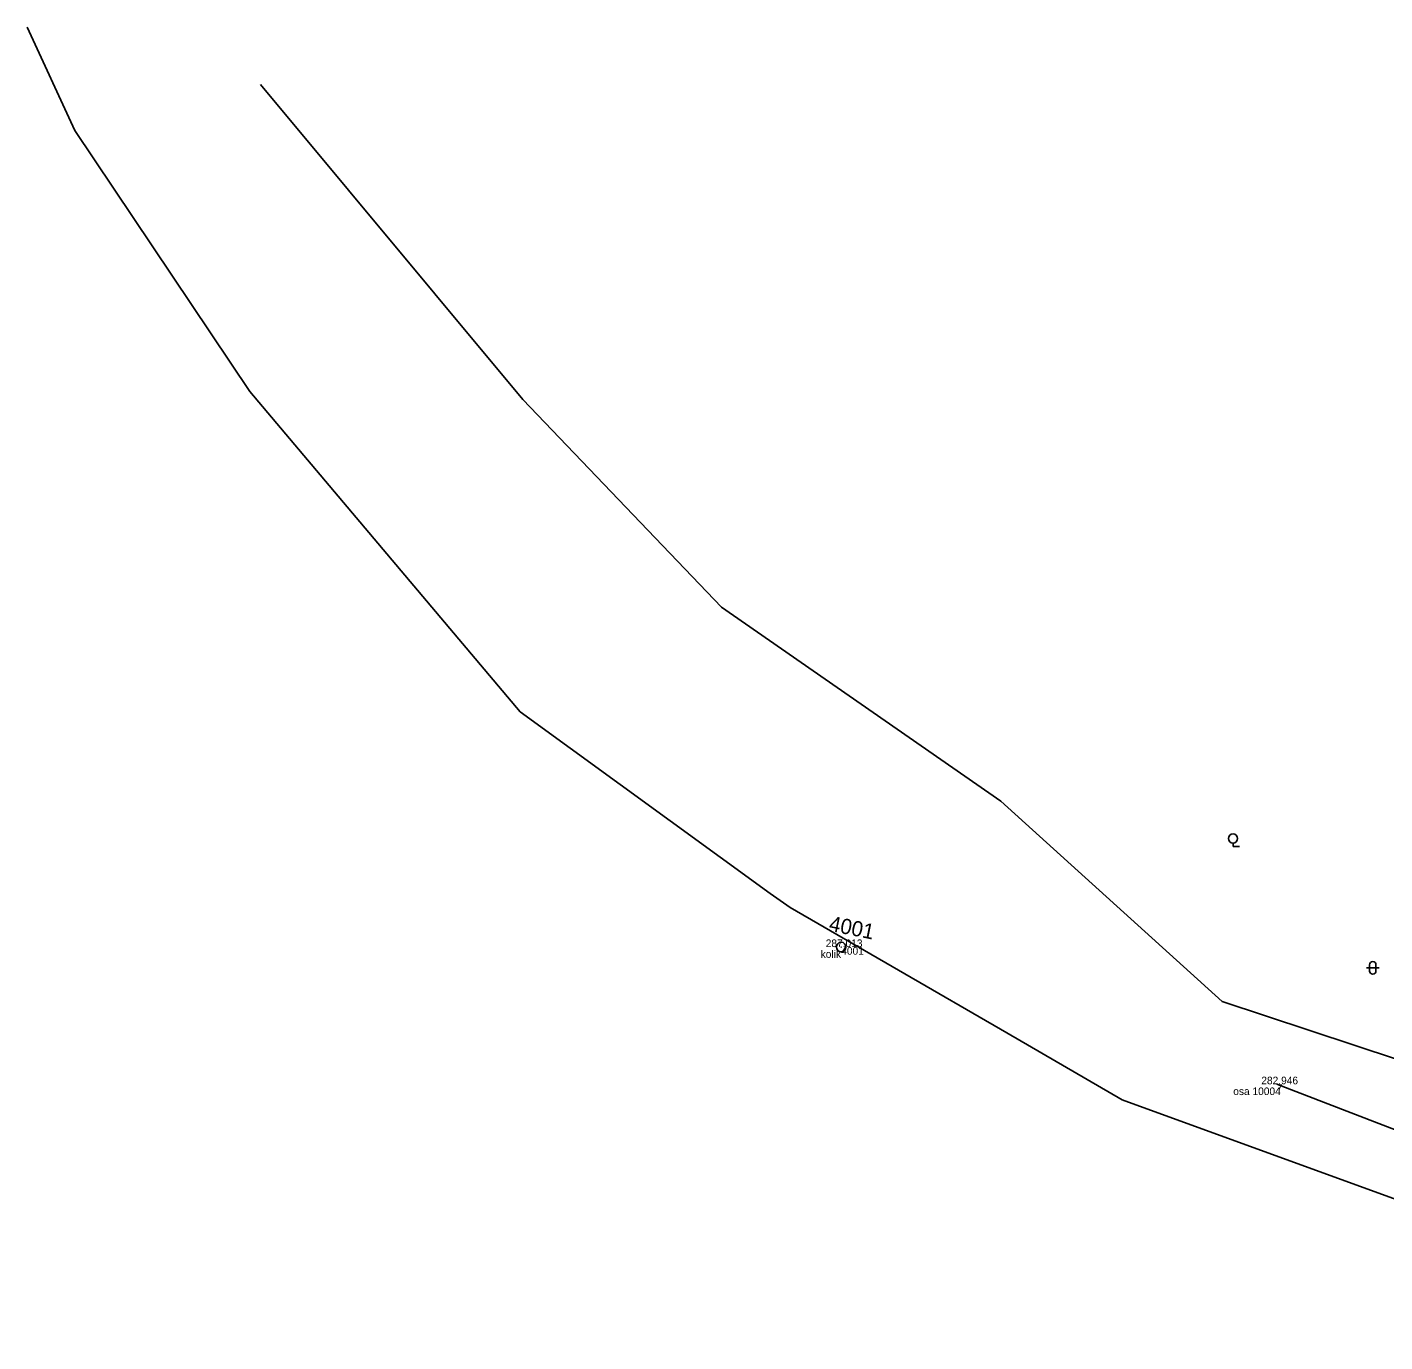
# Model space of a CAD drawing. Extents: x -728659 to -728362, y -1073110 to -1072943.
# Drawn here: x -728658.9 to -728551.8, y -1073046.9 to -1072943.2 of the extents above; entities that cross this region are included whole.
import ezdxf

# ---------------------------------------------------------------- set-up
doc = ezdxf.new("R2010")
doc.units = 0
for name, color, linetype in [('Vrstva 1', 7, 'Continuous'), ('Vrstva 53', 7, 'Continuous'), ('Vrstva 58', 7, 'Continuous'), ('Vrstva 60', 7, 'Continuous'), ('Vrstva 61', 7, 'Continuous'), ('Vrstva 62', 7, 'Continuous'), ('Vrstva 63', 7, 'Continuous')]:
    doc.layers.add(name, color=color, linetype=linetype)

msp = doc.modelspace()

# ---------------------------------------------------------------- linework, layer by layer
at = {"layer": 'Vrstva 1'}
msp.add_lwpolyline([(-728462.11, -1073044.29), (-728486.96, -1073044.61), (-728498.78, -1073043.7), (-728511.7, -1073041.86), (-728514.39, -1073041.36), (-728535.91, -1073035.98), (-728560.37, -1073026.55)], dxfattribs=at)
at = {"layer": 'Vrstva 53'}
msp.add_lwpolyline([(-728658.89, -1072943.19), (-728655.13, -1072951.34), (-728641.33, -1072971.93), (-728620.02, -1072997.18), (-728600.31, -1073011.5), (-728598.74, -1073012.6), (-728581.66, -1073022.5), (-728572.55, -1073027.78), (-728541.12, -1073039.22), (-728509.9, -1073046.86), (-728510.22, -1073036.28), (-728510.71, -1073032.54), (-728543.86, -1073026.9), (-728564.68, -1073020.02), (-728582.13, -1073004.22), (-728604.14, -1072988.92), (-728619.81, -1072972.56), (-728640.48, -1072947.72)], dxfattribs=at)
at = {"layer": 'Vrstva 58'}
for p, q in [((-728563.82, -1073007.53), (-728563.82, -1073007.81)), ((-728563.82, -1073007.81), (-728563.32, -1073007.81)), ((-728553.3, -1073017.37), (-728552.3, -1073017.37)), ((-728553.05, -1073017.12), (-728553.05, -1073017.62)), ((-728552.55, -1073017.12), (-728552.55, -1073017.62))]:
    msp.add_line(p, q, dxfattribs=at)
msp.add_circle((-728563.82, -1073007.17), 0.362, dxfattribs=at)
for centre, start, end in [((-728552.8, -1073017.12), 0, 180), ((-728552.8, -1073017.62), 180, 0)]:
    msp.add_arc(centre, 0.25, start, end, dxfattribs=at)
at = {"layer": 'Vrstva 60'}
for p, q in [((-728594.71, -1073015.73), (-728594.71, -1073015.73)), ((-728560.37, -1073026.55), (-728560.37, -1073026.55))]:
    msp.add_line(p, q, dxfattribs=at)
at = {"layer": 'Vrstva 63'}
msp.add_line((-728594.73, -1073015.73), (-728594.68, -1073015.74), dxfattribs=at)
msp.add_circle((-728594.71, -1073015.73), 0.378, dxfattribs=at)

# ---------------------------------------------------------------- texts
at = {"layer": 'Vrstva 60'}
for s, p in [('4001', (-728594.71, -1073016.33)), ('7', (-728560.37, -1073027.15))]:
    msp.add_text(s, height=0.6, dxfattribs=at).set_placement(p)
at = {"layer": 'Vrstva 61'}
for s, p in [('287.013', (-728595.93, -1073015.73)), ('282.946', (-728561.59, -1073026.55))]:
    msp.add_text(s, height=0.6, dxfattribs=at).set_placement(p)
at = {"layer": 'Vrstva 62'}
for s, p in [('kolik', (-728596.33, -1073016.58)), ('osa 10004', (-728563.8, -1073027.4))]:
    msp.add_text(s, height=0.6, dxfattribs=at).set_placement(p)
at = {"layer": 'Vrstva 63'}
msp.add_text('4001', height=1.2, rotation=348.5433, dxfattribs=at).set_placement((-728595.74, -1073014.43))

doc.saveas('drawing.dxf')
